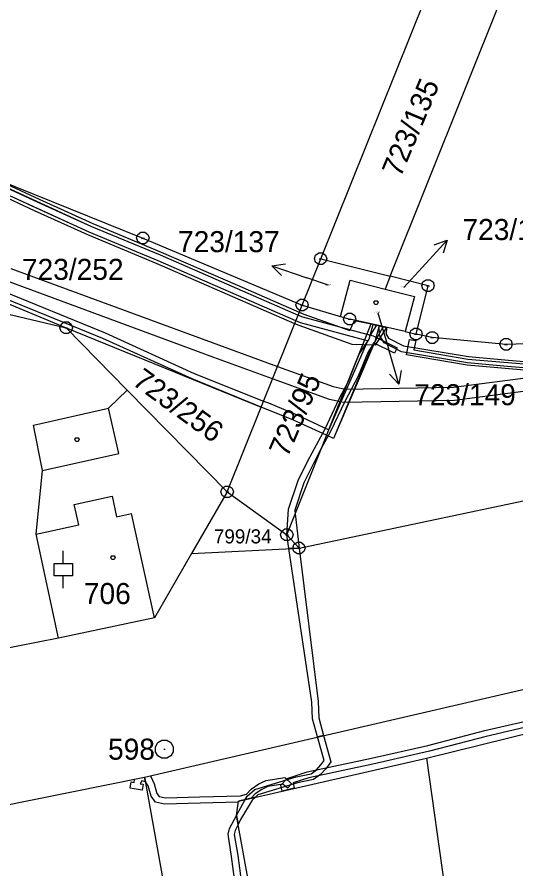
# Model space of a CAD drawing. Extents: x -759060 to -757386, y -1172273 to -1170948.
# Drawn here: x -757658.1 to -757617.8, y -1171174 to -1171105.2 of the extents above; entities that cross this region are included whole.
import ezdxf

# ---------------------------------------------------------------- set-up
doc = ezdxf.new("R2010")
doc.units = 0
for name, color, linetype in [('Vrstva 1', 7, 'Continuous'), ('Vrstva 12', 7, 'Continuous'), ('Vrstva 13', 7, 'Continuous'), ('Vrstva 2', 7, 'Continuous'), ('Vrstva 3', 7, 'Continuous'), ('Vrstva 4', 7, 'Continuous'), ('Vrstva 5', 7, 'Continuous'), ('Vrstva 7', 7, 'Continuous'), ('Vrstva 8', 7, 'Continuous')]:
    doc.layers.add(name, color=color, linetype=linetype)

msp = doc.modelspace()

# ---------------------------------------------------------------- linework, layer by layer
at = {"layer": 'Vrstva 1'}
for p, q in [((-757627.95, -1171126.12), (-757617.67, -1171100.42)), ((-757633.57, -1171124.72), (-757624.34, -1171101.79)), ((-757660.94, -1171117.82), (-757647.94, -1171123.04)), ((-757647.94, -1171123.04), (-757635.07, -1171128.46)), ((-757668.07, -1171124.5), (-757654.14, -1171130.3)), ((-757635.07, -1171128.46), (-757633.57, -1171124.72)), ((-757633.57, -1171124.72), (-757627.95, -1171126.12)), ((-757627.95, -1171126.12), (-757628.37, -1171127.17)), ((-757624.89, -1171126.89), (-757627.95, -1171126.12)), ((-757668.62, -1171126.83), (-757654.14, -1171130.3)), ((-757631.96, -1171129.38), (-757631.19, -1171126.45)), ((-757631.19, -1171126.45), (-757628.37, -1171127.17)), ((-757625.86, -1171130.8), (-757624.89, -1171126.89)), ((-757628.37, -1171127.17), (-757625.99, -1171127.77)), ((-757625.99, -1171127.77), (-757626.74, -1171130.6)), ((-757638.37, -1171136.7), (-757635.07, -1171128.46)), ((-757635.07, -1171128.46), (-757631.96, -1171129.38)), ((-757631.96, -1171129.38), (-757631.22, -1171129.6)), ((-757629.49, -1171129.98), (-757631.22, -1171129.6)), ((-757654.14, -1171130.3), (-757638.37, -1171136.7)), ((-757654.14, -1171130.3), (-757649.21, -1171135.32)), ((-757636.3, -1171147.03), (-757629.49, -1171129.98)), ((-757626.74, -1171130.6), (-757629.49, -1171129.98)), ((-757626.74, -1171130.6), (-757625.86, -1171130.8)), ((-757624.55, -1171131.09), (-757625.86, -1171130.8)), ((-757618.58, -1171131.63), (-757624.55, -1171131.09)), ((-757612.58, -1171131.49), (-757618.58, -1171131.63)), ((-757650.71, -1171136.79), (-757649.21, -1171135.32)), ((-757649.21, -1171135.32), (-757641.12, -1171143.56)), ((-757635.32, -1171148.1), (-757575.38, -1171135.47)), ((-757641.12, -1171143.56), (-757638.37, -1171136.7)), ((-757656.78, -1171138.16), (-757650.71, -1171136.79)), ((-757656.05, -1171141.82), (-757656.78, -1171138.16)), ((-757656.56, -1171146.97), (-757656.05, -1171141.82)), ((-757641.12, -1171143.56), (-757644, -1171148.54)), ((-757641.12, -1171143.56), (-757636.3, -1171147.03)), ((-757654.76, -1171155.39), (-757656.56, -1171146.97)), ((-757636.3, -1171147.03), (-757635.32, -1171148.1)), ((-757644, -1171148.54), (-757635.32, -1171148.1)), ((-757644, -1171148.54), (-757646.99, -1171153.73)), ((-757647.8, -1171166.6), (-757578.4, -1171150.51)), ((-757646.99, -1171153.73), (-757654.76, -1171155.39)), ((-757654.76, -1171155.39), (-757679.3, -1171160.14)), ((-757625.03, -1171165.07), (-757609.52, -1171161.23)), ((-757640.21, -1171168.54), (-757625.03, -1171165.07)), ((-757625.03, -1171165.07), (-757618.21, -1171212.79)), ((-757673.89, -1171171.9), (-757647.8, -1171166.6)), ((-757647.8, -1171166.6), (-757644.69, -1171184.15)), ((-757640.38, -1171169.72), (-757640.21, -1171168.54)), ((-757632.07, -1171215.23), (-757640.38, -1171169.72))]:
    msp.add_line(p, q, dxfattribs=at)
at = {"layer": 'Vrstva 12'}
for p, q in [((-757631.96, -1171129.38), (-757631.19, -1171126.45)), ((-757631.19, -1171126.45), (-757628.37, -1171127.17)), ((-757628.37, -1171127.17), (-757625.99, -1171127.77)), ((-757625.99, -1171127.77), (-757626.74, -1171130.6)), ((-757631.96, -1171129.38), (-757631.22, -1171129.6)), ((-757629.49, -1171129.98), (-757631.22, -1171129.6)), ((-757626.74, -1171130.6), (-757629.49, -1171129.98)), ((-757653.48, -1171144.58), (-757650.43, -1171143.9)), ((-757650.43, -1171143.9), (-757650.07, -1171145.57)), ((-757653.12, -1171146.23), (-757653.48, -1171144.58)), ((-757650.07, -1171145.57), (-757648.87, -1171145.31)), ((-757646.99, -1171153.73), (-757648.87, -1171145.31)), ((-757656.56, -1171146.97), (-757653.12, -1171146.23)), ((-757654.76, -1171155.39), (-757656.56, -1171146.97)), ((-757646.99, -1171153.73), (-757654.76, -1171155.39))]:
    msp.add_line(p, q, dxfattribs=at)
at = {"layer": 'Vrstva 13'}
for p, q in [((-757660.07, -1171118.45), (-757656.42, -1171120.14)), ((-757659.97, -1171118.21), (-757656.32, -1171119.91)), ((-757659.82, -1171118.56), (-757652.08, -1171122.1)), ((-757656.7, -1171120.83), (-757660.32, -1171119.16)), ((-757656.6, -1171120.6), (-757660.23, -1171118.93)), ((-757652.28, -1171122.56), (-757660.23, -1171118.93)), ((-757656.42, -1171120.14), (-757652.08, -1171122.1)), ((-757656.32, -1171119.91), (-757651.98, -1171121.87)), ((-757652.38, -1171122.79), (-757656.7, -1171120.83)), ((-757652.28, -1171122.56), (-757656.6, -1171120.6)), ((-757652.08, -1171122.1), (-757646.54, -1171124.4)), ((-757652.08, -1171122.1), (-757646.54, -1171124.4)), ((-757651.98, -1171121.87), (-757646.45, -1171124.17)), ((-757646.79, -1171125.11), (-757652.38, -1171122.79)), ((-757646.7, -1171124.88), (-757652.28, -1171122.56)), ((-757646.7, -1171124.88), (-757652.28, -1171122.56)), ((-757646.45, -1171124.17), (-757640.3, -1171126.85)), ((-757635.58, -1171129.74), (-757646.7, -1171124.88)), ((-757635.58, -1171129.74), (-757646.7, -1171124.88)), ((-757646.54, -1171124.4), (-757635.39, -1171129.27)), ((-757646.54, -1171124.4), (-757635.39, -1171129.27)), ((-757658.62, -1171125.49), (-757641.83, -1171131.66)), ((-757641.11, -1171127.59), (-757646.79, -1171125.11)), ((-757660.88, -1171126.67), (-757650.99, -1171130.69)), ((-757660.88, -1171126.67), (-757650.99, -1171130.69)), ((-757642.21, -1171132.68), (-757658.96, -1171126.51)), ((-757640.3, -1171126.85), (-757635.3, -1171129.04)), ((-757651.17, -1171131.17), (-757661.08, -1171127.13)), ((-757651.17, -1171131.17), (-757661.08, -1171127.13)), ((-757635.67, -1171129.97), (-757641.11, -1171127.59)), ((-757635.3, -1171129.04), (-757634.94, -1171129.2)), ((-757635.21, -1171129.9), (-757635.58, -1171129.74)), ((-757635.21, -1171129.9), (-757635.58, -1171129.74)), ((-757635.39, -1171129.27), (-757635.05, -1171129.42)), ((-757635.39, -1171129.27), (-757635.05, -1171129.42)), ((-757635.05, -1171129.42), (-757629.83, -1171130.82)), ((-757635.05, -1171129.42), (-757629.83, -1171130.82)), ((-757634.94, -1171129.2), (-757631.21, -1171130.52)), ((-757631.21, -1171130.52), (-757630.83, -1171129.69)), ((-757630.83, -1171129.69), (-757629.49, -1171129.98)), ((-757635.32, -1171130.12), (-757635.67, -1171129.97)), ((-757631.03, -1171131.64), (-757635.32, -1171130.12)), ((-757630.01, -1171131.29), (-757635.21, -1171129.9)), ((-757630.01, -1171131.29), (-757635.21, -1171129.9)), ((-757629.64, -1171131.2), (-757629.32, -1171130.02)), ((-757629.54, -1171130.9), (-757629.02, -1171130.09)), ((-757629.49, -1171129.98), (-757628.25, -1171130.26)), ((-757629.32, -1171130.02), (-757628.83, -1171130.13)), ((-757628.83, -1171130.13), (-757629.18, -1171131.42)), ((-757628.52, -1171130.2), (-757629.18, -1171131.42)), ((-757628.25, -1171130.26), (-757629.16, -1171131.69)), ((-757629.02, -1171130.09), (-757628.52, -1171130.2)), ((-757628.83, -1171130.13), (-757628.25, -1171130.26)), ((-757628.81, -1171130.88), (-757628.83, -1171130.13)), ((-757628.25, -1171130.26), (-757628.29, -1171130.8)), ((-757643.96, -1171134.43), (-757651.17, -1171131.17)), ((-757643.96, -1171134.43), (-757651.17, -1171131.17)), ((-757650.99, -1171130.69), (-757643.79, -1171133.99)), ((-757650.99, -1171130.69), (-757643.79, -1171133.99)), ((-757630.46, -1171132.42), (-757629.64, -1171131.2)), ((-757629.83, -1171130.82), (-757629.54, -1171130.9)), ((-757629.83, -1171130.82), (-757629.34, -1171130.94)), ((-757629.34, -1171130.94), (-757627.39, -1171131.91)), ((-757628.44, -1171131.52), (-757628.81, -1171130.88)), ((-757628.29, -1171130.8), (-757628.08, -1171131.14)), ((-757628.08, -1171131.14), (-757626.87, -1171131.75)), ((-757626.62, -1171132.49), (-757626.38, -1171131.23)), ((-757626.38, -1171131.23), (-757625.89, -1171131.32)), ((-757641.83, -1171131.66), (-757637.05, -1171133.41)), ((-757632.9, -1171138.53), (-757629.77, -1171131.35)), ((-757632.9, -1171138.53), (-757629.77, -1171131.35)), ((-757629.18, -1171131.42), (-757632.54, -1171139.23)), ((-757629.3, -1171131.52), (-757632.54, -1171139.23)), ((-757630.16, -1171131.66), (-757631.03, -1171131.64)), ((-757629.16, -1171131.69), (-757630.16, -1171131.66)), ((-757629.77, -1171131.35), (-757630.01, -1171131.29)), ((-757629.77, -1171131.35), (-757630.01, -1171131.29)), ((-757629.18, -1171131.42), (-757629.74, -1171132.24)), ((-757627.61, -1171132.35), (-757629.3, -1171131.52)), ((-757627.03, -1171132.23), (-757628.44, -1171131.52)), ((-757627.39, -1171131.91), (-757627.61, -1171132.35)), ((-757626.87, -1171131.75), (-757621.63, -1171132.62)), ((-757625.89, -1171131.32), (-757626.03, -1171132.08)), ((-757631.36, -1171134.66), (-757630.46, -1171132.42)), ((-757629.74, -1171132.24), (-757630.55, -1171134.2)), ((-757621.71, -1171133.12), (-757627.03, -1171132.23)), ((-757621.73, -1171133.32), (-757626.62, -1171132.49)), ((-757626.03, -1171132.08), (-757621.67, -1171132.82)), ((-757621.63, -1171132.62), (-757618.39, -1171132.92)), ((-757637.45, -1171134.41), (-757642.21, -1171132.68)), ((-757615.31, -1171133.87), (-757621.73, -1171133.32)), ((-757618.47, -1171133.42), (-757621.71, -1171133.12)), ((-757621.67, -1171132.82), (-757615.31, -1171133.37)), ((-757618.39, -1171132.92), (-757615.31, -1171133.17)), ((-757643.79, -1171133.99), (-757638.18, -1171136.22)), ((-757643.79, -1171133.99), (-757638.18, -1171136.22)), ((-757637.05, -1171133.41), (-757632.55, -1171135.05)), ((-757622.83, -1171135.08), (-757612.72, -1171133.78)), ((-757615.31, -1171133.67), (-757618.47, -1171133.42)), ((-757638.37, -1171136.7), (-757643.96, -1171134.43)), ((-757638.37, -1171136.7), (-757643.96, -1171134.43)), ((-757632.85, -1171136.09), (-757637.45, -1171134.41)), ((-757632.07, -1171136.03), (-757631.36, -1171134.66)), ((-757630.55, -1171134.2), (-757631.63, -1171136.25)), ((-757632.55, -1171135.05), (-757631.59, -1171135.25)), ((-757631.59, -1171135.25), (-757622.83, -1171135.08)), ((-757612.56, -1171134.84), (-757622.75, -1171136.16)), ((-757633.22, -1171138.45), (-757632.07, -1171136.03)), ((-757635.76, -1171137.77), (-757638.37, -1171136.7)), ((-757635.76, -1171137.77), (-757638.37, -1171136.7)), ((-757638.18, -1171136.22), (-757637.8, -1171136.37)), ((-757638.18, -1171136.22), (-757637.8, -1171136.37)), ((-757637.8, -1171136.37), (-757635.56, -1171137.31)), ((-757637.8, -1171136.37), (-757635.56, -1171137.31)), ((-757632, -1171136.27), (-757632.85, -1171136.09)), ((-757631.63, -1171136.25), (-757632.78, -1171138.67)), ((-757631.69, -1171136.33), (-757632, -1171136.27)), ((-757622.75, -1171136.16), (-757631.69, -1171136.33)), ((-757635.56, -1171137.31), (-757632.9, -1171138.53)), ((-757635.56, -1171137.31), (-757632.9, -1171138.53)), ((-757633.09, -1171138.98), (-757635.76, -1171137.77)), ((-757633.09, -1171138.98), (-757635.76, -1171137.77)), ((-757634.6, -1171141.04), (-757633.22, -1171138.45)), ((-757632.78, -1171138.67), (-757633.52, -1171140.06)), ((-757632.54, -1171139.23), (-757633.09, -1171138.98)), ((-757632.54, -1171139.23), (-757633.09, -1171138.98)), ((-757633.52, -1171140.06), (-757634.16, -1171141.26)), ((-757635.38, -1171142.64), (-757634.6, -1171141.04)), ((-757634.16, -1171141.26), (-757634.92, -1171142.82)), ((-757636.16, -1171144.96), (-757635.38, -1171142.64)), ((-757634.92, -1171142.82), (-757635.66, -1171145.04)), ((-757636.3, -1171147.03), (-757636.16, -1171144.96)), ((-757635.66, -1171145.04), (-757635.63, -1171145.34)), ((-757635.63, -1171145.34), (-757635.32, -1171148.1)), ((-757636.13, -1171148.14), (-757636.3, -1171147.03)), ((-757635.32, -1171148.1), (-757636.13, -1171148.14)), ((-757636.13, -1171148.14), (-757635.32, -1171148.1)), ((-757634.28, -1171160.54), (-757636.13, -1171148.14)), ((-757635.32, -1171148.1), (-757633.78, -1171160.5)), ((-757634.23, -1171161.89), (-757634.28, -1171160.54)), ((-757633.78, -1171160.5), (-757633.73, -1171161.81)), ((-757620.31, -1171162.84), (-757612.13, -1171160.95)), ((-757612.03, -1171161.43), (-757620.19, -1171163.32)), ((-757633.82, -1171163.36), (-757634.23, -1171161.89)), ((-757633.73, -1171161.81), (-757633.34, -1171163.25)), ((-757624.9, -1171164.04), (-757620.31, -1171162.84)), ((-757633.82, -1171163.36), (-757633.34, -1171163.25)), ((-757633.34, -1171163.25), (-757633.82, -1171163.36)), ((-757633.3, -1171165.26), (-757633.82, -1171163.36)), ((-757633.34, -1171163.25), (-757632.76, -1171165.36)), ((-757620.19, -1171163.32), (-757624.78, -1171164.52)), ((-757629.46, -1171165.08), (-757624.9, -1171164.04)), ((-757624.78, -1171164.52), (-757629.36, -1171165.56)), ((-757634.65, -1171166.18), (-757629.46, -1171165.08)), ((-757629.36, -1171165.56), (-757634.53, -1171166.66)), ((-757633.92, -1171166.01), (-757633.55, -1171165.62)), ((-757633.55, -1171165.62), (-757633.3, -1171165.26)), ((-757632.76, -1171165.36), (-757633.15, -1171165.94)), ((-757636.28, -1171166.71), (-757634.65, -1171166.18)), ((-757635.56, -1171166.58), (-757634.35, -1171166.34)), ((-757634.35, -1171166.34), (-757633.92, -1171166.01)), ((-757633.15, -1171165.94), (-757633.58, -1171166.39)), ((-757648.98, -1171167.49), (-757648.89, -1171167)), ((-757648.89, -1171167), (-757648.65, -1171167.05)), ((-757648.65, -1171167.05), (-757648.62, -1171166.77)), ((-757648.62, -1171166.77), (-757647.8, -1171166.6)), ((-757648.02, -1171166.92), (-757648.15, -1171167.14)), ((-757647.73, -1171166.98), (-757648.02, -1171166.92)), ((-757647.8, -1171166.6), (-757647.33, -1171166.49)), ((-757647.8, -1171166.6), (-757647.73, -1171166.98)), ((-757647.73, -1171166.98), (-757647.8, -1171166.6)), ((-757647.52, -1171167.32), (-757647.73, -1171166.98)), ((-757647.33, -1171166.49), (-757647.04, -1171167.14)), ((-757638.88, -1171167.6), (-757635.56, -1171166.58)), ((-757638.56, -1171167.16), (-757637.97, -1171166.89)), ((-757637.97, -1171166.89), (-757636.47, -1171166.65)), ((-757636.78, -1171167.27), (-757636.28, -1171166.71)), ((-757636.47, -1171166.65), (-757635.93, -1171167.14)), ((-757634.53, -1171166.66), (-757635.8, -1171167.08)), ((-757634.15, -1171166.8), (-757635.44, -1171167.06)), ((-757633.58, -1171166.39), (-757634.15, -1171166.8)), ((-757648, -1171167.67), (-757648.98, -1171167.49)), ((-757648.15, -1171167.14), (-757647.91, -1171167.18)), ((-757647.91, -1171167.18), (-757648, -1171167.67)), ((-757647.27, -1171168.15), (-757647.52, -1171167.32)), ((-757647.04, -1171167.14), (-757646.81, -1171167.93)), ((-757639.57, -1171167.98), (-757639.18, -1171167.59)), ((-757639.5, -1171168.14), (-757638.88, -1171167.6)), ((-757639.18, -1171167.59), (-757638.56, -1171167.16)), ((-757638.32, -1171167.6), (-757638.86, -1171167.97)), ((-757635.44, -1171167.06), (-757638.64, -1171168.04)), ((-757637.83, -1171167.37), (-757638.32, -1171167.6)), ((-757636.63, -1171167.19), (-757637.83, -1171167.37)), ((-757636.67, -1171167.73), (-757636.78, -1171167.27)), ((-757635.7, -1171167.51), (-757636.67, -1171167.73)), ((-757636.26, -1171167.51), (-757636.63, -1171167.19)), ((-757635.93, -1171167.14), (-757636.26, -1171167.51)), ((-757635.8, -1171167.08), (-757635.7, -1171167.51)), ((-757646.93, -1171168.62), (-757647.27, -1171168.15)), ((-757646.81, -1171167.93), (-757646.63, -1171168.18)), ((-757646.63, -1171168.18), (-757646.15, -1171168.29)), ((-757646.15, -1171168.29), (-757643.34, -1171168.21)), ((-757643.34, -1171168.21), (-757640.06, -1171168.13)), ((-757640.38, -1171169.72), (-757639.66, -1171168.41)), ((-757639.19, -1171168.31), (-757640.21, -1171168.54)), ((-757640.06, -1171168.13), (-757639.57, -1171167.98)), ((-757639.66, -1171168.41), (-757639.5, -1171168.14)), ((-757638.85, -1171168.23), (-757639.66, -1171168.41)), ((-757639.66, -1171168.41), (-757638.85, -1171168.23)), ((-757638.86, -1171167.97), (-757639.19, -1171168.31)), ((-757638.85, -1171168.23), (-757639.12, -1171168.46)), ((-757638.64, -1171168.04), (-757638.85, -1171168.23)), ((-757646.19, -1171168.79), (-757646.93, -1171168.62)), ((-757643.32, -1171168.71), (-757646.19, -1171168.79)), ((-757640.22, -1171168.63), (-757643.32, -1171168.71)), ((-757640.21, -1171168.54), (-757640.22, -1171168.63)), ((-757639.12, -1171168.46), (-757640.05, -1171170.02)), ((-757640.95, -1171170.75), (-757640.38, -1171169.72)), ((-757640.38, -1171169.72), (-757640.25, -1171170.44)), ((-757640.25, -1171170.44), (-757640.38, -1171169.72)), ((-757640.25, -1171170.44), (-757640.47, -1171170.91)), ((-757640.05, -1171170.02), (-757640.25, -1171170.44)), ((-757641.05, -1171171.23), (-757640.95, -1171170.75)), ((-757640.47, -1171170.91), (-757640.55, -1171171.25)), ((-757640.77, -1171173.02), (-757641.05, -1171171.23)), ((-757640.55, -1171171.25), (-757640.27, -1171172.94)), ((-757640.41, -1171175.7), (-757640.77, -1171173.02)), ((-757640.27, -1171172.94), (-757639.91, -1171175.6))]:
    msp.add_line(p, q, dxfattribs=at)
at = {"layer": 'Vrstva 3'}
msp.add_line((-757654.37, -1171149.33), (-757654.37, -1171148.33), dxfattribs=at)
msp.add_lwpolyline([(-757654.37, -1171151.33), (-757654.37, -1171150.33), (-757655.12, -1171150.33), (-757655.12, -1171149.33), (-757654.37, -1171149.33), (-757653.62, -1171149.33), (-757653.62, -1171150.33), (-757654.37, -1171150.33)], dxfattribs=at)
at = {"layer": 'Vrstva 4'}
for p, q in [((-757649.89, -1171140.46), (-757650.71, -1171136.79)), ((-757656.05, -1171141.82), (-757649.89, -1171140.46)), ((-757653.48, -1171144.58), (-757650.43, -1171143.9)), ((-757650.43, -1171143.9), (-757650.07, -1171145.57)), ((-757653.12, -1171146.23), (-757653.48, -1171144.58)), ((-757650.07, -1171145.57), (-757648.87, -1171145.31)), ((-757646.99, -1171153.73), (-757648.87, -1171145.31)), ((-757656.56, -1171146.97), (-757653.12, -1171146.23))]:
    msp.add_line(p, q, dxfattribs=at)
at = {"layer": 'Vrstva 5'}
for points in [[(-757629, -1171128.1), (-757628.91, -1171128.25), (-757629, -1171128.4), (-757629.18, -1171128.4), (-757629.27, -1171128.25), (-757629.18, -1171128.1)], [(-757653.17, -1171139.18), (-757653.08, -1171139.33), (-757653.17, -1171139.48), (-757653.35, -1171139.48), (-757653.44, -1171139.33), (-757653.35, -1171139.18)], [(-757650.27, -1171148.71), (-757650.18, -1171148.86), (-757650.27, -1171149.01), (-757650.45, -1171149.01), (-757650.54, -1171148.86), (-757650.45, -1171148.71)]]:
    msp.add_lwpolyline(points, close=True, dxfattribs=at)
at = {"layer": 'Vrstva 7'}
for p, q in [((-757623.352, -1171123.199), (-757625.38, -1171125.41)), ((-757637.526, -1171125.273), (-757634.69, -1171126.25)), ((-757626.86, -1171127.03), (-757625.38, -1171125.41)), ((-757632.94, -1171126.85), (-757634.69, -1171126.25)), ((-757628.96, -1171129.08), (-757628.1, -1171131.97)), ((-757627.247, -1171134.846), (-757628.1, -1171131.97))]:
    msp.add_line(p, q, dxfattribs=at)
for points in [[(-757624.397, -1171123.598), (-757623.352, -1171123.199), (-757623.66, -1171124.274)], [(-757636.744, -1171126.071), (-757637.526, -1171125.273), (-757636.418, -1171125.126)], [(-757627.052, -1171133.745), (-757627.247, -1171134.846), (-757628.01, -1171134.03)]]:
    msp.add_lwpolyline(points, dxfattribs=at)
at = {"layer": 'Vrstva 8'}
for p, q in [((-757648.06, -1171123.04), (-757647.82, -1171123.04)), ((-757633.69, -1171124.72), (-757633.45, -1171124.72)), ((-757625.01, -1171126.89), (-757624.77, -1171126.89)), ((-757635.19, -1171128.46), (-757634.95, -1171128.46)), ((-757631.34, -1171129.6), (-757631.1, -1171129.6)), ((-757654.26, -1171130.3), (-757654.02, -1171130.3)), ((-757625.98, -1171130.8), (-757625.74, -1171130.8)), ((-757624.67, -1171131.09), (-757624.43, -1171131.09)), ((-757618.7, -1171131.63), (-757618.46, -1171131.63)), ((-757641.24, -1171143.56), (-757641, -1171143.56)), ((-757636.42, -1171147.03), (-757636.18, -1171147.03)), ((-757635.44, -1171148.1), (-757635.2, -1171148.1)), ((-757646.25, -1171164.35), (-757646.15, -1171164.35))]:
    msp.add_line(p, q, dxfattribs=at)
for points in [[(-757647.79, -1171122.56), (-757647.54, -1171122.74), (-757647.44, -1171123.03), (-757647.54, -1171123.32), (-757647.79, -1171123.5), (-757648.1, -1171123.5), (-757648.35, -1171123.32), (-757648.45, -1171123.03), (-757648.35, -1171122.74), (-757648.1, -1171122.56)], [(-757633.42, -1171124.24), (-757633.17, -1171124.42), (-757633.07, -1171124.71), (-757633.17, -1171125), (-757633.42, -1171125.18), (-757633.73, -1171125.18), (-757633.98, -1171125), (-757634.08, -1171124.71), (-757633.98, -1171124.42), (-757633.73, -1171124.24)], [(-757624.74, -1171126.41), (-757624.49, -1171126.59), (-757624.39, -1171126.88), (-757624.49, -1171127.17), (-757624.74, -1171127.35), (-757625.05, -1171127.35), (-757625.3, -1171127.17), (-757625.4, -1171126.88), (-757625.3, -1171126.59), (-757625.05, -1171126.41)], [(-757634.92, -1171127.98), (-757634.67, -1171128.16), (-757634.57, -1171128.45), (-757634.67, -1171128.74), (-757634.92, -1171128.92), (-757635.23, -1171128.92), (-757635.48, -1171128.74), (-757635.58, -1171128.45), (-757635.48, -1171128.16), (-757635.23, -1171127.98)], [(-757631.07, -1171129.12), (-757630.82, -1171129.3), (-757630.72, -1171129.59), (-757630.82, -1171129.88), (-757631.07, -1171130.06), (-757631.38, -1171130.06), (-757631.63, -1171129.88), (-757631.73, -1171129.59), (-757631.63, -1171129.3), (-757631.38, -1171129.12)], [(-757653.99, -1171129.82), (-757653.74, -1171130), (-757653.64, -1171130.29), (-757653.74, -1171130.58), (-757653.99, -1171130.76), (-757654.3, -1171130.76), (-757654.55, -1171130.58), (-757654.65, -1171130.29), (-757654.55, -1171130), (-757654.3, -1171129.82)], [(-757625.71, -1171130.32), (-757625.46, -1171130.5), (-757625.36, -1171130.79), (-757625.46, -1171131.08), (-757625.71, -1171131.26), (-757626.02, -1171131.26), (-757626.27, -1171131.08), (-757626.37, -1171130.79), (-757626.27, -1171130.5), (-757626.02, -1171130.32)], [(-757624.4, -1171130.61), (-757624.15, -1171130.79), (-757624.05, -1171131.08), (-757624.15, -1171131.37), (-757624.4, -1171131.55), (-757624.71, -1171131.55), (-757624.96, -1171131.37), (-757625.06, -1171131.08), (-757624.96, -1171130.79), (-757624.71, -1171130.61)], [(-757618.43, -1171131.15), (-757618.18, -1171131.33), (-757618.08, -1171131.62), (-757618.18, -1171131.91), (-757618.43, -1171132.09), (-757618.74, -1171132.09), (-757618.99, -1171131.91), (-757619.09, -1171131.62), (-757618.99, -1171131.33), (-757618.74, -1171131.15)], [(-757640.97, -1171143.08), (-757640.72, -1171143.26), (-757640.62, -1171143.55), (-757640.72, -1171143.84), (-757640.97, -1171144.02), (-757641.28, -1171144.02), (-757641.53, -1171143.84), (-757641.63, -1171143.55), (-757641.53, -1171143.26), (-757641.28, -1171143.08)], [(-757636.15, -1171146.55), (-757635.9, -1171146.73), (-757635.8, -1171147.02), (-757635.9, -1171147.31), (-757636.15, -1171147.49), (-757636.46, -1171147.49), (-757636.71, -1171147.31), (-757636.81, -1171147.02), (-757636.71, -1171146.73), (-757636.46, -1171146.55)], [(-757635.17, -1171147.62), (-757634.92, -1171147.8), (-757634.82, -1171148.09), (-757634.92, -1171148.38), (-757635.17, -1171148.56), (-757635.48, -1171148.56), (-757635.73, -1171148.38), (-757635.83, -1171148.09), (-757635.73, -1171147.8), (-757635.48, -1171147.62)], [(-757646.01, -1171163.63), (-757645.67, -1171163.82), (-757645.48, -1171164.16), (-757645.48, -1171164.55), (-757645.67, -1171164.89), (-757646.01, -1171165.08), (-757646.4, -1171165.08), (-757646.74, -1171164.89), (-757646.93, -1171164.55), (-757646.93, -1171164.16), (-757646.74, -1171163.82), (-757646.4, -1171163.63)]]:
    msp.add_lwpolyline(points, close=True, dxfattribs=at)

# ---------------------------------------------------------------- texts
at = {"layer": 'Vrstva 2'}
for s, rotation, p in [('723/135', 67.26524, (-757627.113, -1171118.202)), ('723/256', 324.00763, (-757648.888, -1171134.821)), ('723/95', 66.63499, (-757636.251, -1171140.838))]:
    msp.add_text(s, height=1.7, rotation=rotation, dxfattribs=at).set_placement(p)
for s, height, p in [('723/252', 1.7, (-757657.716, -1171126.42)), ('723/137', 0.1, (-757633.212, -1171126.85)), ('723/138', 0.1, (-757627.136, -1171127.03)), ('723/149', 0.1, (-757629.23, -1171129.08)), ('799/34', 1.14, (-757642.201, -1171147.72)), ('706', 1.7, (-757652.711, -1171152.62))]:
    msp.add_text(s, height=height, dxfattribs=at).set_placement(p)
at = {"layer": 'Vrstva 7'}
for s, p in [('723/138', (-757622.113, -1171123.2)), ('723/137', (-757645.1, -1171124.18)), ('723/149', (-757626.013, -1171136.55))]:
    msp.add_text(s, height=1.7, dxfattribs=at).set_placement(p)
at = {"layer": 'Vrstva 8'}
msp.add_text('598', height=1.7, dxfattribs=at).set_placement((-757650.758, -1171165.2))

doc.saveas('drawing.dxf')
